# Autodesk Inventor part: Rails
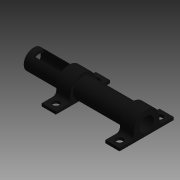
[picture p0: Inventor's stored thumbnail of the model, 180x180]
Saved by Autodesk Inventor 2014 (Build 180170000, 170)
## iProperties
Created: 2013-09
Part Number: Rails
Material: Generic
Document SubType Name: Modeling
Designer: Joey Mason
Appearance: Black Control Joints
Author: Joey Mason
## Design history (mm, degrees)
sketch "Sketch1"
  geometry: C1 r 6.477 at (0, 0); C2 r 8.89 at (0, 0); 1 further point
  constraints: 2 centre point, 2 coincident
  dimensions: "d0" = 12.954 diameter of C1; "d1" = 17.78 diameter of C2
extrude "Extrusion1" new body sketch "Sketch1" distance "d2" = 101.6; taper "d3" = 0 deg
sketch "Sketch2"
  geometry: L1 (0, 0)-(-5.08, 0); L2 (-5.08, 0)-(-5.08, 5.08); L3 (-5.08, 5.08)-(-5.08, -5.08); L4 (-5.08, 5.08)-(-30.48, 5.08); L5 (-30.48, 5.08)-(-30.48, -4.329); L6 (-30.48, -4.329)-(-5.08, -4.329); L7 (-5.08, -4.329)-(-5.08, 5.08)
  constraints: 14 end point, 3 perpendicular, 2 horizontal, 2 parallel
  dimensions: "d4" = 5.08 distance of L1.start L1.end; "d5" = 5.08 distance of L1.end L2.end; "d6" = 10.16 distance of L2.end L3.end; "d7" = 25.4 distance of L6.end L5.end
extrude "Extrusion2" cut sketch "Sketch2" distance "d8" = 101.6; taper "d9" = 0 deg
workplane "Work Plane1"
sketch "Sketch3"
  geometry: L1 (0, -11.43)-(-8.89, -11.43); L2 (-8.89, -11.43)-(-8.89, 11.43); L3 (-8.89, 11.43)-(0, 11.43); L4 (-8.89, -11.43)-(-6.35, -11.43); L5 (-6.35, -11.43)-(-6.35, -24.13); L6 (-6.35, -24.13)-(-8.89, -24.13); L7 (-8.89, -24.13)-(-8.89, -11.43); L8 (-8.89, 11.43)-(-6.35, 11.43); L9 (-6.35, 11.43)-(-8.89, 11.43); L10 (-8.89, 11.43)-(-8.89, 24.457); L11 (-8.89, 24.457)-(-6.35, 24.457); L12 (-6.35, 24.457)-(-6.35, 11.43); C1 r 6.477 at (0, 0); A1 r 11.43 centre (0, 0) between (0, -11.43) and (0, 11.43); 1 further point
  constraints: 24 end point, 3 parallel, 3 perpendicular, 2 centre point, 2 coincident, 2 point on circle, 2 point on line, 2 tangent, 1 horizontal
  dimensions: "d11" = 12.954 diameter of C1; "d12" = 22.86 diameter of A1; "d13" = 8.89 distance of L1.start L1.end; "d14" = 2.54 distance of L1.end L4.end; "d15" = 12.7 distance of L4.end L5.end; "d16" = 2.54 distance of L2.end L8.end; "d17" = 2.54 distance of L10.end L11.end
extrude "Extrusion3" join sketch "Sketch3" stored distance "d18" = 12.7; taper "d19" = 0 deg
workplane "Work Plane2"
sketch "Sketch4"
  geometry: L1 (-6.35, 11.43)-(-6.35, 24.457) reference; L2 (-8.89, 24.457)-(-8.89, 0) reference; L3 (-6.35, 24.457)-(-8.89, 24.457) reference; L4 (0, 11.43)-(-6.35, 11.43) reference; L5 (-6.35, -11.43)-(0, -11.43) reference; L6 (-6.35, -24.13)-(-6.35, -11.43) reference; L7 (-8.89, 24.457)-(-8.89, 0) reference; L8 (-8.89, 0)-(-8.89, -24.13) reference; L9 (-8.89, -24.13)-(-6.35, -24.13) reference; L10 (-6.35, -24.13)-(-6.35, -11.43) reference; L11 (-6.35, -11.43)-(0, -11.43) reference; L12 (0, 11.43)-(-6.35, 11.43) reference; L13 (-6.35, 11.43)-(-6.35, 24.457) reference; L14 (-6.35, 24.457)-(-8.89, 24.457) reference; C1 r 6.477 at (0, 0) reference; C2 r 8.89 at (0, 0) reference; A1 r 11.43 centre (0, 0) between (0, -11.43) and (0, 11.43) reference; 2 further points
  constraints: 1 horizontal alignment
extrude "Extrusion4" join sketch "Sketch4" distance "d21" = 12.7; taper "d22" = 0 deg
sketch "Sketch5"
  geometry: L1 (69.85, 12.7)-(69.85, 0) reference; L2 (69.85, 12.7)-(57.15, 12.7) reference; L3 (57.15, 0)-(57.15, 12.7) reference; L4 (69.85, 0)-(57.15, 0) reference; L5 (0, -35.887)-(12.7, -35.887) reference; L6 (12.7, -22.86)-(12.7, -35.887) reference; L7 (12.7, -22.86)-(0, -22.86) reference; L8 (0, -35.887)-(0, -22.86) reference; L9 (69.85, -22.86)-(69.85, -35.887) reference; L10 (69.85, -22.86)-(57.15, -22.86) reference; L11 (57.15, -35.887)-(57.15, -22.86) reference; L12 (69.85, -35.887)-(57.15, -35.887) reference; C1 r 3.048 at (63.5, 6.35); C2 r 3.048 at (6.35, 6.35); C3 r 3.048 at (6.35, -29.373); C4 r 3.048 at (63.5, -29.373); 1 further point
  constraints: 4 centre point
  dimensions: "d23" = 6.096 diameter of C1; "d24" = 6.096 diameter of C2; "d25" = 6.096 diameter of C3; "d26" = 6.096 diameter of C4
extrude "Extrusion5" cut sketch "Sketch5" distance "d27" = 12.7; taper "d28" = 0 deg
fillet "Fillet1" dims "d29" = 3.175
body "Solid1"
node "Projected Loop1"
node "Projected Loop2"
node "Projected Loop3"
node "Projected Loop4"
node "Projected Loop5"
other parameters: "d10" = 38.1, "d20" = 63.5
